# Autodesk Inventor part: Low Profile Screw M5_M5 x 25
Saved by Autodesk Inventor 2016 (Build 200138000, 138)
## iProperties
Created: 2016-01
Part Number: Low Profile Screw M5_M5 x 25
Material: Generic
Document SubType Name: Modeling
Designer: John
Density: 1 g/cm^3
Appearance: Default
Author: John
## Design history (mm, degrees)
feature "CUT-EXTRUDE2"
body "Solid1"
